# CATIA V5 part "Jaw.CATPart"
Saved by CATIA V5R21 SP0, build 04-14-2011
Part number: Part 2
Bounding box of the stored display mesh (mm): x 0 to 20, y -45 to 45, z -25 to 40
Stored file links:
  D:\CATIA V5R21 E-RESOURCES\CATIA-V5R21\catia-v5r21-prt\c16-catia-v5r20-prt\Prismatic Joint-(Fig16-14)\CAT_V5R21_Jaw.CATPart
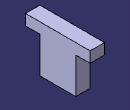
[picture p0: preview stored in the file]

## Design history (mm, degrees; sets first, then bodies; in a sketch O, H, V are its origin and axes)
Body1 (main body)
  Sketch1 on yz-plane, origin (0, 0, 0), H (0, 1, 0), V (0, 0, 1)
    line L1 (25, 25) -> (25, -25)
    line L2 (25, -25) -> (-25, -25)
    line L3 (-25, -25) -> (-25, 25)
    point P1 (25, 25)
    point P4 (-25, 25)
    line L4 (-25, 25) -> (-45, 25)
    point P5 (-45, 25)
    line L5 (-45, 25) -> (-45, 40)
    line L6 (-45, 40) -> (45, 40)
    line L7 (25, 25) -> (45, 25)
    point P8 (45, 25)
    line L8 (45, 25) -> (45, 40)
    reference intersected line E1 through (0, 0) direction (-1, 0) from xy-plane
    reference intersected line E3 through (0, 0) direction (0, 1) from zx-plane
    length L1 = 50
    distance V L1 = 25
    distance H L2 = 25
    distance E1 L6 = 40
    distance P1 P8 = 20
    distance P4 P5 = 20
    vertical: L1 V, L3 V, L5 V, L8 V, E3 V
    horizontal: L2 H, L4 H, L6 H, L7 H, E1 H
    equidistance: L1 L3 O
    perpendicularity: E1 L1
    coincidence: P1 L4, P4 L7, P5 L7, P8 L4, L4 L7
  Pad1: profile Sketch1, direction (1, 0, 0), length 20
